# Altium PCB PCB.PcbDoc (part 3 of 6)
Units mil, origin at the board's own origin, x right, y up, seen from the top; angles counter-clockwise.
Board outline 7100 x 7000 mil, 4 copper layers (Top Layer, GND, VCC, Bottom Layer), stack 61.2 mil thick; 759 components, 507 nets, 2200 pads, 452 vias.
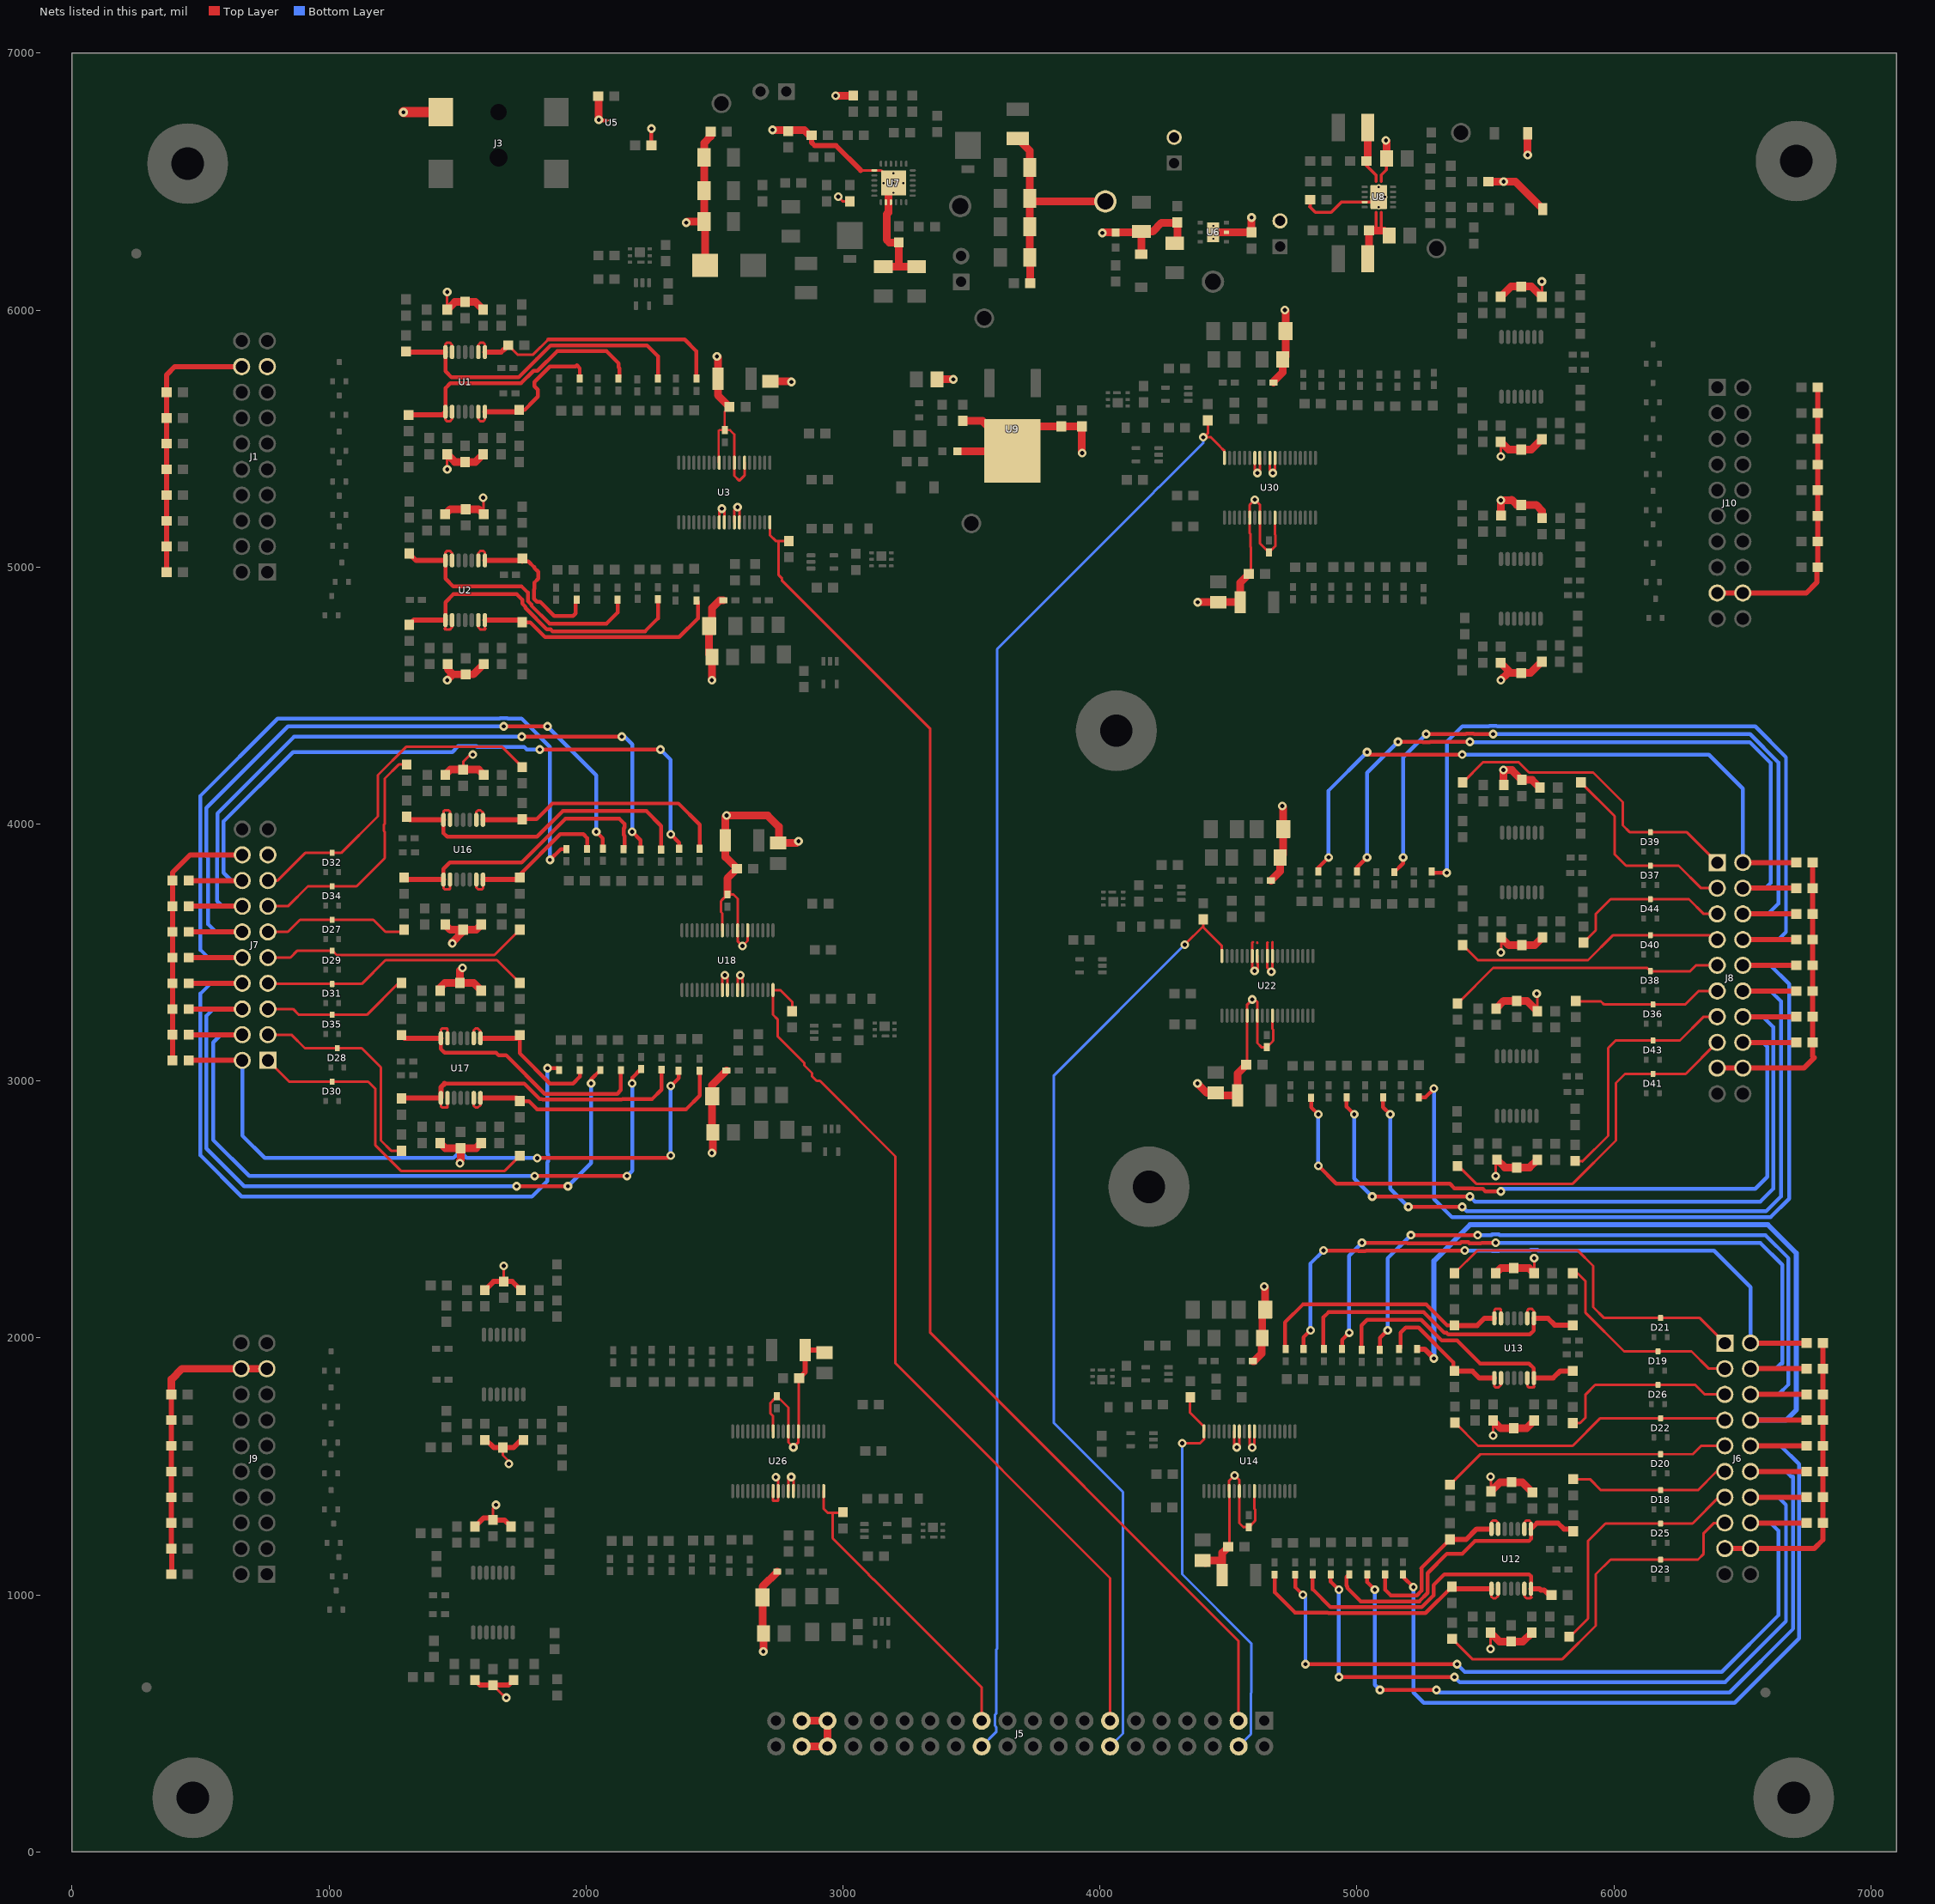
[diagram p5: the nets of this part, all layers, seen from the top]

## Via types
v1: diameter 34, hole 16, Top Layer to Bottom Layer, 440 vias
v2: diameter 19.68, hole 7.87, Top Layer to Bottom Layer, 11 vias
v3: diameter 30, hole 14, Top Layer to Bottom Layer, 1 vias

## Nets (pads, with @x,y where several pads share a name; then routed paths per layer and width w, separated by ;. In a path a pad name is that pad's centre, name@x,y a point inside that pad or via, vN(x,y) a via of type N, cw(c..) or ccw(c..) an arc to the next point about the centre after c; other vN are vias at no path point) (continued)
AGND: C1.1 C2.1 C3.1 C4.1 C5.2 C6.2 C7.2 C11.1 C12.1 C17.1 C18.1 C24.2 C25.2 C26.2 C30.1 C31.1 C35.1 C36.1 C39.2 C40.2 C41.2 C42.2 C43.2 C44.2 C45.2 C46.2 C47.2 C48.2 C49.1 C51.1 C53.2 C54.2 C55.2 C56.2 C57.2 C58.2 C59.2 C60.2 C62.1 C63.2 C64.2 C66.2 C67.2 C68.1 C69.2 C72.2 C73.2 C74.2 C76.1 C77.1 C78.1 C79.1 C80.2 C81.2 C82.2 C86.1 C87.1 C92.1 C93.1 C99.2 C100.2 C101.2 C105.1 C106.1 C110.1 C111.1 C114.1 C115.1 C116.1 C117.1 C118.2 C119.2 C120.2 C124.1 C125.1 C130.1 C131.1 C137.2 C138.2 C139.2 C143.1 C144.1 C148.1 C149.1 C152.1 C153.1 C154.1 C155.1 C156.2 C157.2 C158.2 C162.1 C163.1 C168.1 C169.1 C175.2 C176.2 C177.2 C181.1 C182.1 C186.1 C187.1 C190.1 C191.1 C192.1 C193.1 C194.2 C195.2 C196.2 C200.1 C201.1 C206.1 C207.1 C213.2 C214.2 C215.2 C219.1 C220.1 C224.1 C225.1 C228.1 C229.1 C230.1 C231.1 C232.2 C233.2 C234.2 C238.1 C239.1 C244.1 C245.1 C251.2 C252.2 C253.2 C257.1 C258.1 C262.1 C263.1 C272.2 C273.2 D11.2 D12.2 D13.2 D14.1 D17.2 J1.17 J1.18 J3.2 J5.35 J5.36 J5.37 J5.38 J6.17 J6.18 J7.17 J7.18 J8.17 J8.18 J9.17 J9.18 J10.17 J10.18 J11.2 J12.2 L2.2 R5.1 R6.1 R7.1 R8.1 R9.1 R10.1 R11.1 R12.1 R50.2 R63.1 R70.1 R77.1 R78.1 R79.1 R80.1 R81.1 R82.1 R83.1 R84.1 R122.1 R123.1 R124.1 R125.1 R126.1 R127.1 R128.1 R129.1 R167.1 R168.1 R169.1 R170.1 R171.1 R172.1 R173.1 R174.1 R212.1 R213.1 R214.1 R215.1 R216.1 R217.1 R218.1 R219.1 R257.1 R258.1 R259.1 R260.1 R261.1 R262.1 R263.1 R264.1 R313.1 R318.1 R323.1 R328.1 R333.1 R338.1 TP3.1 U3.6 U3.8 U3.11 U3.28 U3.29 U3.31 U3.32 U5.B1 U6.2 U6.7 U7.2 U7.3 U7.19 U7.25 U8.4 U8.11@5085.39,6440 U9.4@3660,5451.57 U14.6 U14.8 U14.11 U14.28 U14.29 U14.31 U14.32 U18.6 U18.8 U18.11 U18.28 U18.29 U18.31 U18.32 U22.6 U22.8 U22.11 U22.28 U22.29 U22.31 U22.32 U26.6 U26.8 U26.11 U26.28 U26.29 U26.31 U26.32 U30.6 U30.8 U30.11 U30.28 U30.29 U30.31 U30.32 | length 28220.3
  Top Layer w6: 2079,6738.19 U5.B1@2092.13,6738.19
  Top Layer w8: U3.11@2518.57,5406.14 2516.67,5408.05 2516.67,5437.83 2515.76,5437.83 2515.76,5530.26 2519.5,5534 2520.88,5532.62 R313.1@2540,5532.62 ; C26.2@2558.5,5623.26 2540,5604.75 R313.1@2540,5532.62 ; 2577.63,5516 2561.01,5532.62 R313.1@2540,5532.62
  Top Layer w10: v1(1460,5380) C3.1@1460,5438.82 ; C35.1@1460,6001.81 v1(1460,6070) ; C114.1@1522.36,4211.5 1522.36,4242.36 1550,4270 v1(1560,4270) ; v1(1600,5270) 1602,5268 C30.1@1602,5205.18 ; C201.1@1638.26,648.45 1676.71,610 1680,610 v1(1690,600) ; C191.1@1638.26,1291.45 1638.26,1338.26 v1(1650,1350) ; C200.1@1676.96,1572.9 1676.96,1543.04 1700,1520 v1(1700,1510) ; C190.1@1679.76,2219.42 1680,2219.67 v1(1680,2280) ; v1(2050,6740) 2060,6740 v1@2061.81,6738.19 ; U3.28@2518.57,5173.86 2518.57,5216.57 v1(2529,5227) 2538.26,5217.74 U3.29@2538.26,5173.86 ; U18.28@2530.93,3353.8 2530.93,3401.93 v1(2541,3412) 2550.62,3402.38 U18.29@2550.62,3353.8 ; U18.11@2530.93,3586.09 2530.93,3651.68 2525.32,3657.3 2525.32,3699.46 2529.12,3703.27 2529.12,3705.08 2529.46,3705.08 R323.1@2550,3725.62 2573.98,3725.62 2590.63,3708.97 2590,3600.92 U18.8@2589.08,3600 ; U3.31@2577.63,5173.86 2577.63,5220.63 v1(2590,5233) 2597.31,5225.69 U3.32@2597.31,5173.86 ; 2577.63,5516 U3.8@2577.63,5406.14 2577.63,5355.37 2597,5336 2617,5356 U3.6@2617,5406.14 ; U18.31@2589.99,3353.8 2589.99,3401.99 2600,3412 v1(2601,3412) 2601,3411 2609.67,3402.33 U18.32@2609.67,3353.8 ; U18.8@2589.99,3586.09 2589.99,3544.01 v1(2609,3525) 2629.36,3545.36 U18.6@2629.36,3586.09 ; U26.28@2728.57,1403.81 2728.57,1366.72 2728.26,1366.41 2748.26,1366.41 U26.29@2748.26,1403.81 2748.26,1448.74 v1(2739,1458) ; U26.11@2728.57,1636.09 2728.57,1697.76 2725.86,1697.76 2718.32,1705.3 2718.32,1747.46 2725.86,1755 2728.57,1755 2728.57,1759.19 R333.1@2743,1773.62 2787.63,1729 U26.8@2787.63,1636.09 2787.63,1593.37 v1(2807,1574) 2827,1594 U26.6@2827,1636.09 ; U26.31@2787.63,1403.81 2787.63,1452.11 2794.52,1459 v1(2799,1459) 2799,1454.52 2807.31,1446.21 U26.32@2807.31,1403.81 U26.32@2808.22,1404.71 ; U26.6@2826.09,1639.95 2827.9,1641.76 2827.9,1841.41 C215.2@2829.75,1843.26 ; v1(2982,6441) 2982,6440 2998.93,6423.07 R50.2@3026.93,6423.07 ; 3066.22,6543.78 U7.19@3122.13,6543.78 3147.72,6543.78 v2(3196.93,6494.57) 3187.09,6484.73 U7.25@3187.09,6456.18 ; C101.2@4499.5,1187 4504.21,1191.71 4504.21,1402.95 U14.6@4503.31,1403.86 4503.31,1444.31 v1(4524,1465) 4525,1465 4542.68,1447.32 U14.8@4542.68,1403.86 4542.68,1279.01 4559.5,1262.19 4560.87,1263.57 R318.1@4580,1263.57 4603.21,1286.78 4603.54,1286.78 4603.54,1288.59 4604.68,1289.73 4604.68,1331.89 4601.73,1334.84 U14.11@4601.73,1403.86 ; U14.32@4522.99,1636.14 4522.99,1584.01 v1(4533,1574) 4542.68,1583.68 U14.31@4542.68,1636.14 ; C177.2@4569.5,3063 4573.31,3066.8 U22.6@4573.31,3254.17 4573.31,3297.31 v1(4593,3317) 4603,3317 4612.68,3307.32 U22.8@4612.68,3254.17 4612.68,3147.32 4628.62,3131.38 R328.1@4650,3131.38 4673.21,3154.59 4673.54,3154.59 4673.54,3156.4 4674.69,3157.54 4674.69,3199.7 4671.73,3202.66 U22.11@4671.73,3254.17 ; C253.2@4579.5,4973 4588.5,4982 4588.5,5075.32 4586.77,5077.05 4586.77,5127.95 4582.13,5132.6 4582.13,5162.89 4582.24,5163.01 4582.24,5168.6 4584.06,5170.41 U30.6@4584.06,5180 ; U14.29@4582.05,1636.14 4582.05,1582.95 4592,1573 v1(4593,1573) 4593,1574 4601.73,1582.73 U14.28@4601.73,1636.14 ; U30.6@4583.15,5192.44 4583.15,5242.15 v1(4603,5262) 4622.52,5242.48 U30.8@4622.52,5192.44 4622.52,5091.86 R338.1@4658,5056.38 4658,5056.75 4682.69,5081.43 4682.69,5124.7 4681.57,5125.81 U30.11@4681.57,5192.44 ; 4595.49,3540.92 4592.99,3538.42 U22.32@4592.99,3486.46 4592.99,3437.01 v1(4602,3428) 4605,3428 4614,3437 4614,3456.61 4613.58,3457.02 4613.58,3485.55 U22.31@4612.68,3486.46 ; U30.32@4602.83,5424.72 4602.83,5376.17 v1(4613,5366) 4622.52,5375.52 U30.31@4622.52,5424.72 ; 4612,3538 4612.68,3537.32 ; 4653,3539 4652.05,3538.05 U22.29@4652.05,3486.46 4652.05,3439.95 v1(4667,3425) 4671.73,3429.73 U22.28@4671.73,3486.46 4671.73,3539.27 4671,3540 ; U30.29@4661.89,5424.72 4661.89,5376.11 4672,5366 v1(4673,5366) 4673,5367 4681.57,5375.57 U30.28@4681.57,5424.72 ; v1(5520,790) 5520.73,790.73 C106.1@5520.73,852.95 ; v1(5520,1460) 5522.05,1457.95 C92.1@5522.05,1403.19 ; v1(5530,1620) C105.1@5530,1678.5 ; v1(5540,2630) 5540,2688.48 C182.1@5545,2693.49 ; v1@5559.69,4560.31 v1(5560,4560) ; C257.1@5559.69,5487.48 5559.69,5430.31 v1(5560,5430) ; v1(5560,3500) 5562.05,3502.05 C181.1@5562.05,3558.5 ; C79.1@5690,2251.5 v1(5690,2310) ; v1(5700,3340) 5702.05,3337.95 C154.1@5702.05,3271.5 ; C231.1@5719.69,6051.5 5720,6051.81 v1(5720,6111.02)
  Top Layer w12: C67.2@4818.5,6430 4818.5,6405.24 4816,6402.73 4838.73,6380 4900,6380 4940.31,6420.31 U8.4@5030.28,6420.31 5065.71,6420.31 U8.11@5085.39,6440 ; C63.2@5036.89,6580 5036.89,6563.11 5075.55,6524.45 5075.55,6500.24 ; 5070,6310 5075.55,6315.55 5075.55,6379.76 ; 5087.7,6310 5095.24,6317.54 5095.24,6379.76 ; 5095.24,6500.24 5095.24,6525.24 5115.39,6545.39 C64.2@5115.39,6590
  Top Layer w15: v1@2061.81,6738.19 2079,6738.19 ; C272.2@2254.5,6641 2254.5,6693.5 v1@2255,6694
  Top Layer w20: R7.1@368.5,4980 R8.1@368.5,5080 R9.1@368.5,5180 R10.1@368.5,5280 R11.1@368.5,5380 R12.1@368.5,5480 R5.1@368.5,5580 R6.1@368.5,5680 368.5,5748.5 400,5780 J1.18@660,5780 ; R213.1@386.76,1779.95 R212.1@386.76,1679.95 R219.1@386.76,1579.95 R218.1@386.76,1479.95 R217.1@386.76,1379.95 R216.1@386.76,1279.95 386.76,1181.62 388.43,1179.95 R214.1@388.43,1079.95 ; R124.1@390.87,3080 R125.1@390.87,3180 R126.1@390.87,3280 R127.1@390.87,3380 R128.1@390.87,3480 R129.1@390.87,3580 R122.1@390.87,3680 R123.1@390.87,3780 390.87,3810.87 460,3880 J7.18@662.36,3880 ; C193.1@1568.26,668.45 1588.26,648.45 C201.1@1638.26,648.45 1698.26,648.45 C207.1@1718.26,668.45 ; C225.1@1568.26,1265.9 1602.31,1299.95 1629.75,1299.95 C191.1@1638.26,1291.45 1682.71,1291.45 C219.1@1708.26,1265.9 ; C224.1@1606.96,2185.9 1640.48,2219.42 C190.1@1679.76,2219.42 1713.43,2219.42 C220.1@1746.96,2185.9 ; C192.1@1609.76,1604.93 1641.79,1572.9 C200.1@1676.96,1572.9 1717.73,1572.9 C206.1@1749.76,1604.93 ; C194.2@2687.08,854.2 C194.2@2691.33,849.95 ; C215.2@2829.75,1843.26 2853.22,1866.72 C214.2@2853.22,1953.26 2918.26,1953.26 C213.2@2928.26,1943.26 ; C51.1@2878.5,6680 2878.5,6651.5 2890,6640 2970,6640 ; 2972.78,6640 3069,6543.78 ; J8.17@6402.05,3050 J8.18@6502.05,3050 6739.69,3050 6779.69,3090 6773.54,3096.14 R168.1@6773.54,3150 R167.1@6773.54,3250 R174.1@6773.54,3350 R173.1@6773.54,3450 R172.1@6773.54,3550 R171.1@6773.54,3650 R170.1@6773.54,3750 R169.1@6773.54,3850 ; J10.17@6402.05,4898.98 J10.18@6502.05,4898.98 6748.98,4898.98 6790,4940 6790,4995.43 R258.1@6793.54,4998.98 R257.1@6793.54,5098.98 R264.1@6793.54,5198.98 R263.1@6793.54,5298.98 R262.1@6793.54,5398.98 R261.1@6793.54,5498.98 R260.1@6793.54,5598.98 R259.1@6793.54,5698.98 ; J6.17@6432.05,1180 J6.18@6532.05,1180 6779.69,1180 6813.54,1213.86 R78.1@6813.54,1280 R77.1@6813.54,1380 R84.1@6813.54,1480 R83.1@6813.54,1580 R82.1@6813.54,1680 R81.1@6813.54,1780 R80.1@6813.54,1880 R79.1@6813.54,1980
  Top Layer w30: R213.1@386.76,1779.95 386.76,1838.45 428.26,1879.95 J9.18@658.26,1879.95 J9.17@758.26,1879.95 ; C117.1@1432.36,2758.5 1452.36,2738.5 C125.1@1512.36,2738.5 ; C149.1@1432.36,3351.5 1432.36,3362.36 1451.5,3381.5 C115.1@1510,3381.5 ; C36.1@1452,5205.18 1472,5225.18 C2.1@1532,5225.18 1582,5225.18 C30.1@1602,5205.18 ; C116.1@1452.36,3608.5 1472.36,3588.5 C124.1@1522.36,3588.5 ; C148.1@1452.36,4191.5 1472.36,4211.5 C114.1@1522.36,4211.5 1582.36,4211.5 C144.1@1602.36,4191.5 ; v1(1460,4560) 1482.19,4582.19 ; C3.1@1460,5438.82 1490,5408.82 C11.1@1530,5408.82 1570,5408.82 C17.1@1600,5438.82 ; C35.1@1460,6001.81 1490,6031.81 C1.1@1530,6031.81 1570,6031.81 C31.1@1600,6001.81 ; C4.1@1462,4622.19 1462,4602.38 1482.19,4582.19 ; v1(1480,3535) 1480,3540 1522.36,3582.36 C124.1@1522.36,3588.5 ; v1(1510,2680) 1510,2690 1512.36,2692.36 C125.1@1512.36,2738.5 ; v1(1520.05,3440) 1510,3429.95 C115.1@1510,3381.5 ; C131.1@1592.36,2758.5 1572.36,2738.5 C125.1@1512.36,2738.5 ; C143.1@1592.36,3351.5 1562.36,3381.5 C115.1@1510,3381.5 ; C130.1@1592.36,3608.5 1572.36,3588.5 C124.1@1522.36,3588.5 ; C18.1@1602,4622.19 1562,4582.19 C12.1@1532,4582.19 1482.19,4582.19 ; C273.2@2048.5,6827 2050,6825.5 v1(2050,6740) ; v1(2390,6340) 2394.25,6344.25 C45.2@2459.84,6344.25 ; C42.2@2463.43,6174.25 2463.43,6340.67 C45.2@2459.84,6344.25 ; C46.2@2485.43,6694.25 2485.43,6675.43 2459.84,6649.84 C43.2@2459.84,6594.25 C44.2@2459.84,6464.25 C45.2@2459.84,6344.25 ; v1(2490,2720) 2493.69,2723.69 C118.2@2493.69,2799.95 2491.18,2802.46 C119.2@2491.18,2940 2491.18,2984.18 C120.2@2547,3040 ; v1(2490,4560) C5.2@2490,4650 2478.82,4661.18 C6.2@2478.82,4770 2490,4781.18 2490,4840 2520,4870 C7.2@2534.63,4870 ; v1(2510,5820) 2513.3,5816.7 C25.2@2513.3,5733.26 2513.3,5668.47 C26.2@2558.5,5623.26 ; R323.1@2550,3725.62 2550,3788.39 C139.2@2587.87,3826.26 2542.66,3871.47 C138.2@2542.66,3936.26 2542.66,4028.66 v1(2547,4033) 2707,4033 2751,3989 2751,3929.64 C137.2@2747.62,3926.26 2820.26,3926.26 v1(2827,3933) ; C194.2@2687.08,854.2 C195.2@2687.08,989.95 2687.08,1032.39 C196.2@2744.63,1089.95 ; v1(2690,780) 2691.33,781.33 C194.2@2691.33,849.95 ; C24.2@2718.26,5723.26 2796.74,5723.26 v1(2800,5720) ; v1(2726,6701) 2781.99,6701 C60.2@2786.93,6696.06 2790.87,6700 2850.02,6700 2870.02,6680 C51.1@2878.5,6680 ; J5.38@2840,410 J5.36@2940,410 J5.35@2940,510 J5.37@2840,510 ; v1(2972,6834) 2980.47,6834 2981.24,6834.76 C49.1@3040,6834.76 ; C47.2@3156.93,6168.74 3220,6168.74 ; U7.25@3187.09,6484.73 3178,6475.64 3178,6431 3177,6430 3177,6380 3170,6373 3170,6274 3180.93,6263.07 C55.2@3216.93,6263.07 3216.93,6171.81 3220,6168.74 ; C56.2@3286.93,6168.74 3220,6168.74 ; R70.1@3366.18,5730.39 3429.61,5730.39 v1(3430,5730) ; D17.2@3445.71,5450.39 3658.82,5450.39 U9.4@3660,5451.57 ; C72.2@3466.18,5568.9 3542.68,5568.9 U9.4@3660,5451.57 ; L2.2@3680,6667.48 3727.09,6620.4 C57.2@3727.09,6554.57 C58.2@3727.09,6434.57 ; C53.2@3731.4,6101.6 C53.2@3728.43,6104.57 3728.43,6203.23 C54.2@3727.09,6204.57 C59.2@3727.09,6324.57 C58.2@3727.09,6434.57 ; v1(3931,5444) 3930,5445 C74.2@3930,5547.2 C73.2@3850,5547.2 3755.63,5547.2 U9.4@3660,5451.57 ; v1(4010,6300) 4012.28,6302.28 D13.2@4061.32,6302.28 4157.93,6302.28 C39.2@4161.32,6305.67 ; TP3.1@4021.32,6422.76 3738.9,6422.76 C58.2@3727.09,6434.57 ; D12.2@4161.32,6217.22 C39.2@4161.32,6305.67 ; C41.2@4291.32,6259.84 4301.32,6269.84 C40.2@4301.32,6341.26 4300.06,6340 4240,6340 4205.67,6305.67 C39.2@4161.32,6305.67 ; v1(4380,2990) 4417,2953 C175.2@4451,2953 4461,2943 C176.2@4536.04,2943 4536.04,3029.54 C177.2@4569.5,3063 ; v1(4381,4863) C251.2@4461,4863 C252.2@4546.04,4863 4546.04,4939.54 C253.2@4579.5,4973 ; C99.2@4410,1124 C99.2@4400,1134 4474.04,1134 4476.04,1136 ; U6.7@4441.32,6302.76 U6.2@4492.3,6302.76 4589.55,6302.76 C48.2@4590,6302.3 v1(4590,6360) ; C100.2@4476.04,1077 4476.04,1136 ; C101.2@4499.5,1187 4476.04,1163.54 4476.04,1136 ; C82.2@4595.67,1910 4600,1910 4630,1940 4630,1997.95 C80.2@4632.05,2000 4632.05,2098.82 C81.2@4643.23,2110 4643.23,2196.77 v1(4640,2200) ; C158.2@4665.67,3780 4702.05,3816.38 C156.2@4702.05,3870 4713.23,3881.18 C157.2@4713.23,3980 4713.23,4066.77 v1(4710,4070) ; C234.2@4675.51,5718.26 4675.51,5721.73 4711.89,5758.11 C232.2@4711.89,5808.26 4723.07,5819.44 C233.2@4723.07,5918.26 4723.07,5996.93 v1(4720,6000) ; C63.2@5036.89,6580 5042.48,6585.59 C62.1@5042.48,6710 ; C68.1@5042.48,6200 5046.89,6204.41 C69.2@5046.89,6310 5070,6310 5087.7,6310 5105.39,6310 C66.2@5125.39,6290 ; v1(5113,6660) 5115.39,6657.61 C64.2@5115.39,6590 ; R63.1@5511.5,6500 v1(5571,6500) 5616.47,6500 D14.1@5723.47,6393 ; C106.1@5520.73,852.95 5555.18,818.5 C76.1@5600.73,818.5 5646.28,818.5 C110.1@5680.73,852.95 ; C92.1@5522.05,1403.19 5557.6,1438.74 C86.1@5602.05,1438.74 5643.35,1438.74 C78.1@5683.35,1398.74 ; C105.1@5530,1678.5 5560,1648.5 C77.1@5610,1648.5 5660,1648.5 C111.1@5690,1678.5 ; C93.1@5540,2251.5 5560,2271.5 C87.1@5610,2271.5 5670,2271.5 C79.1@5690,2251.5 ; C168.1@5542.05,3281.5 5572.05,3311.5 C162.1@5622.05,3311.5 5662.05,3311.5 C154.1@5702.05,3271.5 ; C182.1@5545,2693.49 5575.54,2662.95 C152.1@5622.05,2662.95 5672.05,2662.95 C186.1@5702.05,2692.95 ; C258.1@5559.69,4627.48 5599.69,4587.48 ; C257.1@5559.69,5487.48 5589.69,5457.48 C229.1@5639.69,5457.48 5679.69,5457.48 C263.1@5719.69,5497.48 ; C245.1@5559.69,6051.5 5599.69,6091.5 C239.1@5639.69,6091.5 5679.69,6091.5 C231.1@5719.69,6051.5 ; v1(5560,4560) 5587.48,4587.48 5599.69,4587.48 ; C244.1@5560.98,5200.47 5560,5201.46 v1(5560,5260) 5599.93,5260 5602.05,5262.13 5602.29,5262.13 5622.92,5241.5 C238.1@5640,5241.5 5697.46,5241.5 5720.98,5217.97 C230.1@5720.98,5190.47 ; C181.1@5562.05,3558.5 5592.05,3528.5 C153.1@5642.05,3528.5 5692.05,3528.5 C187.1@5722.05,3558.5 ; C169.1@5572.05,4151.5 5570,4153.54 v1(5570,4210) 5603.54,4210 C163.1@5642.05,4171.5 5682.05,4171.5 C155.1@5712.05,4141.5 ; D11.2@5664.47,6688 5664.47,6605.53 5666,6604 v1(5665,6603) ; C262.1@5719.69,4631.93 5675.24,4587.48 C228.1@5639.69,4587.48 5599.69,4587.48
  Top Layer w40: v1(1290,6770) 1290.08,6770.08 J3.2@1435.59,6770.08
  other v1: 2255,6706
  other v2: 4441.32,6277.76 4441.32,6327.76 5085.39,6400.63 5060.79,6440 5110,6440 3196.93,6456.18 5085.39,6479.37 3158.54,6494.57 3235.32,6494.57 3196.93,6532.95
AO0+: C13.1 R13.1 U1.8 U1.9 | length 1146.8
  Top Layer w10: U1.8@1453.23,5604.17 1453.23,5573.54 1460,5566.77 1470,5566.77 1478.82,5575.59 U1.9@1478.82,5604.17
  Top Layer w15: U1.8@1453.23,5604.17 1453.23,5696.23 1472,5715 1746.87,5715 1795.87,5764 1811.65,5764 1887.65,5840 2080,5840 2127.63,5792.37 2127.63,5776.59 2130,5774.22 2130,5737.87 R13.1@2125.76,5733.62
  Top Layer w20: C13.1@1310,5591.81 1440.87,5591.81 U1.8@1453.23,5604.17
AO1+: C22.1 R15.1 U1.13 U1.14 | length 632.3
  Top Layer w10: U1.13@1581.18,5604.17 1581.18,5575.59 1590,5566.77 1600,5566.77 1606.77,5573.54 U1.14@1606.77,5604.17
  Top Layer w15: C22.1@1740,5611.81 1761.81,5611.81 1800,5650 1800,5650.22 1813.37,5663.59 1813.37,5690.41 1800,5703.78 1800,5720 1860,5780 1960,5780 1965,5785 1975.78,5774.22 R15.1@1975.78,5733.62
  Top Layer w20: U1.14@1606.77,5604.17 1732.36,5604.17 C22.1@1740,5611.81
AO2+: C32.1 R22.1 U2.1 U2.2 | length 678.2
  Top Layer w10: U2.2@1581.18,5025.83 1581.18,5054.41 1590,5063.23 1600,5063.23 1606.77,5056.46 U2.1@1606.77,5025.83
  Top Layer w15: C32.1@1752,5022.19 1775.81,5022.19 1798.81,4999.19 1798.81,4996.98 1814.37,4981.41 1814.37,4954.59 1798.81,4939.02 1798.81,4914.59 1797.63,4913.41 1797.63,4876.59 1810,4864.22 1821.78,4864.22 1876,4810 1950,4810 1960,4820 1960,4868.84 R22.1@1963.5,4872.34
  Top Layer w20: U2.1@1606.77,5025.83 1748.36,5025.83 C32.1@1752,5022.19
AO3+: C38.1 R25.1 U2.6 U2.7 | length 1146.9
  Top Layer w10: U2.7@1453.23,5025.83 1453.23,5056.46 1460,5063.23 1470,5063.23 1478.82,5054.41 U2.6@1478.82,5025.83
  Top Layer w15: U2.7@1453.23,5025.83 1453.23,4954.77 1483.93,4924.07 1750,4924.07 1772.07,4902 1774.75,4902 1774.75,4867.12 1787.13,4854.74 1787.13,4850.53 1857.65,4780 2080,4780 2123.52,4823.52 R25.1@2123.52,4872.34
  Top Layer w20: C38.1@1312,5052.19 1338.36,5025.83 U2.7@1453.23,5025.83
AO4+: C14.1 R27.1 U2.8 U2.9 | length 1321.4
  Top Layer w10: U2.8@1453.23,4793.54 1453.23,4763.23 1450,4760 1453.86,4756.14 1470,4756.14 1478.82,4764.96 U2.9@1478.82,4793.54
  Top Layer w15: U2.8@1453.23,4793.54 1453.23,4863.23 1484,4894 1731,4894 1751.88,4873.12 1751.88,4857.64 1764.25,4845.27 1764.25,4841.05 1848.18,4757.13 1862.87,4757.13 1870,4750 2230,4750 2280,4800 R27.1@2280,4873.98
  Top Layer w20: C14.1@1312,4775.18 1330.36,4793.54 U2.8@1453.23,4793.54
AO5+: C23.1 R29.1 U2.13 U2.14 | length 1056.7
  Top Layer w10: U2.13@1581.18,4793.54 1581.18,4764.96 1590,4756.14 1606.14,4756.14 1610,4760 1606.77,4763.23 U2.14@1606.77,4793.54
  Top Layer w15: C23.1@1752,4785.18 1782.47,4785.18 1840.53,4727.13 2363.01,4727.13 2435.89,4800 2435.89,4864.06 R29.1@2430,4869.95
  Top Layer w20: U2.14@1606.77,4793.54 1743.64,4793.54 C23.1@1752,4785.18
AO6+: C33.1 R31.1 U1.1 U1.2 | length 1090.6
  Top Layer w10: U1.2@1581.18,5836.46 1581.18,5865.04 1590,5873.86 1600,5873.86 1606.77,5867.09 U1.1@1606.77,5836.46 ; C33.1@1697.5,5863 1733.5,5827 1794.65,5827 1853.4,5885.75
  Top Layer w15: 1853.4,5885.75 2384.25,5885.75 2430,5840 R31.1@2430,5733.06
  Top Layer w20: U1.1@1606.77,5836.46 1670.14,5836.46 1679.55,5845.87 1680.38,5845.87 C33.1@1697.5,5863
AO7+: C37.1 R33.1 U1.6 U1.7 | length 1312.8
  Top Layer w10: U1.7@1453.23,5836.46 1453.23,5867.09 1460,5873.86 1470,5873.86 1478.82,5865.04 U1.6@1478.82,5836.46
  Top Layer w15: U1.7@1453.23,5836.46 1453.23,5761.77 1477.13,5737.87 1737.39,5737.87 1807.64,5808.12 1808.12,5808.12 1862.87,5862.87 2237.13,5862.87 2280,5820 2280,5750 2280.21,5749.79 R33.1@2280.21,5733.62
  Top Layer w20: C37.1@1300,5838.82 1302.36,5836.46 U1.7@1453.23,5836.46
B0+: D18.3 J6.11 R73.1 | length 637.8
  Top Layer w10: R73.1@5842.05,1450.24 5907.16,1450.24 5950,1407.4 D18.3@6182.05,1407.4 6327.09,1407.4 6399.69,1480 J6.11@6432.05,1480
B0-: J6.12 R84.2 R86.1 | length 3170.5
  Top Layer w15: R86.1@5040,1080 5040,1050 v1(5070,1020) ; v1(5090,630) v1(5310,630)
  Top Layer w20: J6.12@6532.05,1480 R84.2@6750.55,1480
  Bottom Layer w15: v1(5070,1020) 5070,650 v1(5090,630) ; v1(5310,630) 5320,620 6450,620 6698.15,868.15 6698.15,1460 6690,1460 6670,1480 J6.12@6532.05,1480
B1+: D20.3 J6.9 R90.1 | length 1132.7
  Top Layer w10: R90.1@5362.05,1428.74 5480.71,1547.4 D20.3@6182.05,1547.4 6307.09,1547.4 6339.69,1580 J6.9@6432.05,1580
B1-: J6.10 R83.2 R89.1 | length 3212.7
  Top Layer w15: R89.1@5180,1080 5180,1070 v1(5220,1030)
  Top Layer w20: J6.10@6532.05,1580 R83.2@6750.55,1580
  Bottom Layer w15: v1(5220,1030) 5220,620 5260,580 6470,580 6721.02,831.02 6721.02,1508.54 6649.57,1580 J6.10@6532.05,1580
B2+: D22.3 J6.7 R107.1 | length 1134.9
  Top Layer w10: R107.1@5382.05,1670.14 5472.18,1580 5840,1580 5947.4,1687.4 D22.3@6182.05,1687.4 6424.65,1687.4 J6.7@6432.05,1680
B2-: J6.8 R82.2 R96.1 | length 2997.2
  Top Layer w20: R96.1@5234.45,1956.42 5263.58,1956.42 v1(5300,1920) ; J6.8@6532.05,1680 R82.2@6750.55,1680
  Bottom Layer w20: v1(5300,1920) 5300,2300 5440,2440 6600,2440 6710,2330 6710,1720 6670,1680 J6.8@6532.05,1680
B3+: D26.3 J6.5 R116.1 | length 721.9
  Top Layer w10: R116.1@5840,1668.5 5868.5,1668.5 5890,1690 5890,1780 5927.4,1817.4 D26.3@6172.05,1817.4 6316.69,1817.4 6354.09,1780 J6.5@6432.05,1780
B3-: J6.6 R81.2 R98.1 | length 2879.7
  Top Layer w15: R98.1@5088.5,1953.62 5088.5,1968.5 5090,1970 5090,2000 v1(5120,2030) ; v1(5210,2400) v1(5470,2400)
  Top Layer w20: J6.6@6532.05,1780 R81.2@6750.55,1780
  Bottom Layer w15: v1(5120,2030) 5120,2310 v1(5210,2400) ; v1(5470,2400) 5524.22,2400 5526.59,2402.37 5553.41,2402.37 5555.78,2400 6590,2400 6680,2310 6680,1818.7 6641.3,1780 J6.6@6532.05,1780
B4+: D19.3 J6.3 R75.1 | length 817.8
  Top Layer w10: R75.1@5840,2251.5 5858.5,2251.5 5890,2220 5890,2097.25 6039.85,1947.4 D19.3@6172.05,1947.4 6302.28,1947.4 6369.69,1880 J6.3@6432.05,1880
B4-: J6.4 R80.2 R100.1 | length 2856.9
  Top Layer w15: R100.1@4942.5,1956.42 4942.5,1992.5 v1(4970,2020) ; v1(5020,2370) 5194.22,2370 5196.59,2367.63 5401.84,2367.63 5406.59,2372.37 5433.41,2372.37 5438.16,2367.63 5483.41,2367.63 5485.78,2370 v1(5540,2370)
  Top Layer w20: J6.4@6532.05,1880 R80.2@6750.55,1880
  Bottom Layer w15: v1(4970,2020) 4970,2320 v1(5020,2370) ; v1(5540,2370) 6570,2370 6655.28,2284.72 6655.28,1900 6650,1900 6630,1880 J6.4@6532.05,1880
B5+: D21.3 J6.1 R92.1 | length 1331.4
  Top Layer w10: R92.1@5380,2251.5 5468.38,2339.87 5860.13,2339.87 5920,2280 5920,2120 5962.6,2077.4 D21.3@6182.05,2077.4 6334.65,2077.4 J6.1@6432.05,1980
B5-: J6.2 R79.2 R102.1 | length 2578.9
  Top Layer w15: R102.1@4792.5,1956.42 4792.5,2002.5 v1(4820,2030) ; v1(4870,2340) 5004.22,2340 5006.59,2337.63 5033.41,2337.63 5035.78,2340 v1(5420,2340)
  Top Layer w20: J6.2@6532.05,1980 R79.2@6750.55,1980
  Bottom Layer w15: v1(4820,2030) 4820,2290 v1(4870,2340) ; v1(5420,2340) 5524.22,2340 5526.59,2337.63 5553.41,2337.63 5555.78,2340 5674.22,2340 5676.59,2342.37 5703.41,2342.37 5705.78,2340 6390,2340 6532.05,2197.95 J6.2@6532.05,1980
B6+: D23.3 J6.15 R109.1 | length 1477.4
  Top Layer w10: R109.1@5370.73,828.5 5449.23,750 5800,750 5930,880 5930,1080 5987.4,1137.4 D23.3@6182.05,1137.4 6327.09,1137.4 6349.69,1160 6349.69,1240 6389.69,1280 J6.15@6432.05,1280
B6-: J6.16 R78.2 R104.1 | length 2977.7
  Top Layer w15: R104.1@4760,1078.7 4760,1030 v1(4790,1000) ; v1(4800,730) v1(5390,730)
  Top Layer w20: J6.16@6532.05,1280 R78.2@6750.55,1280
  Bottom Layer w15: v1(4790,1000) 4800,990 v1(4800,730) ; v1(5390,730) 5420,700 6420,700 6640,920 6640,1250 6610,1280 J6.16@6532.05,1280
B7+: D25.3 J6.13 R112.1 | length 1002.7
  Top Layer w10: R112.1@5830.73,838.5 5900,907.78 5900,1210 5967.4,1277.4 D25.3@6182.05,1277.4 6306.22,1277.4 6408.82,1380 J6.13@6432.05,1380
B7-: J6.14 R77.2 R106.1 | length 3081.5
  Top Layer w15: R106.1@4898.21,1080 4898.21,1051.79 v1(4930,1020) ; v1(4930,680) v1(5380,680)
  Top Layer w20: J6.14@6532.05,1380 R77.2@6750.55,1380
  Bottom Layer w15: v1(4930,680) v1(4930,1020) ; v1(5380,680) 5400,660 6432.91,660 6670,897.09 6670,1350 6640,1380 J6.14@6532.05,1380
BO0+: C88.1 R85.1 U12.8 U12.9 | length 1251.3
  Top Layer w10: U12.9@5651.91,1256.14 5651.91,1281.91 5660,1290 5670,1290 5677.5,1282.5 U12.8@5677.5,1256.14
  Top Layer w15: R85.1@4970,1080 4960,1070 4960,1035.78 4962.37,1033.41 4962.37,1027.63 5015.25,974.75 5242.88,974.75 5275.25,1007.12 5275.25,1084.75 5275,1085 5350,1160 5410,1160 5460,1210 5670,1210 5677.5,1217.5 U12.8@5677.5,1256.14
  Top Layer w20: U12.8@5677.5,1256.14 5700.72,1279.36 5782.64,1279.36 5805.86,1256.14 5825.23,1256.14 5830.5,1250.87 5838.43,1250.87 C88.1@5842.05,1247.24
BO1+: C97.1 R87.1 U12.13 U12.14 | length 729.1
  Top Layer w10: U12.14@5523.96,1256.14 5523.96,1283.96 5530,1290 5540,1290 5549.55,1280.45 U12.13@5549.55,1256.14
  Top Layer w15: R87.1@5110,1080 5110,1020 5132.37,997.63 5233.41,997.63 5252.37,1016.59 5252.37,1075.28 5252.13,1075.53 5252.13,1094.47 5252.37,1094.72 5252.37,1101.33 5250,1103.7 C97.1@5362.05,1215.75
  Top Layer w20: C97.1@5362.05,1215.75 5425.75,1215.75 5466.14,1256.14 U12.14@5523.96,1256.14
BO2+: C107.1 R94.1 U13.1 U13.2 | length 628.6
  Top Layer w10: U13.1@5535.28,1843.86 5535.28,1811.18 5540,1806.46 5550,1806.46 5560.87,1817.32 U13.2@5560.87,1843.86
  Top Layer w15: R94.1@5164.45,1956.42 5170,1961.97 5170,2020 5190,2040 5240,2040 5375,1905 5375,1876.5 C107.1@5380,1871.5
  Top Layer w20: C107.1@5380,1871.5 5381.5,1870 5450,1870 5476.14,1843.86 U13.1@5535.28,1843.86
BO3+: C113.1 R97.1 U13.6 U13.7 | length 1148.3
  Top Layer w10: U13.6@5663.23,1843.86 5663.23,1813.23 5670,1806.46 5686.46,1806.46 5690,1810 5688.82,1811.18 U13.7@5688.82,1843.86
  Top Layer w15: R97.1@5018.5,1953.62 5018.5,2048.5 5040,2070 5250,2070 5330,1990 5390,1990 5480,1900 5670,1900 5688.82,1881.18 U13.7@5688.82,1843.86
  Top Layer w20: U13.7@5688.82,1843.86 5763.86,1843.86 5791.5,1871.5 C113.1@5840,1871.5
BO4+: C89.1 R99.1 U13.8 U13.9 | length 1295.2
  Top Layer w10: U13.9@5663.23,2076.14 5663.23,2106.77 5670,2113.54 5680,2113.54 5688.82,2104.72 U13.8@5688.82,2076.14
  Top Layer w15: R99.1@4872.5,1956.42 4870,1958.93 4870,2080 4890,2100 5260,2100 5340,2020 5348.38,2020 5354.93,2013.44 5673.44,2013.44 5688.82,2028.82 U13.8@5688.82,2076.14
  Top Layer w20: U13.8@5688.82,2076.14 5743.86,2076.14 5770,2050 5838.5,2050 C89.1@5840,2048.5
BO5+: C98.1 R101.1 U13.13 U13.14 | length 1089.1
  Top Layer w10: U13.14@5535.28,2076.14 5535.28,2108.82 5540,2113.54 5556.46,2113.54 5560.87,2109.13 U13.13@5560.87,2076.14
  Top Layer w15: R101.1@4722.5,1956.42 4720,1958.93 4720,2060 4790,2130 5270,2130 5351.5,2048.5 C98.1@5380,2048.5
  Top Layer w20: C98.1@5380,2048.5 5468.5,2048.5 5496.14,2076.14 U13.14@5535.28,2076.14
BO6+: C108.1 R103.1 U12.1 U12.2 | length 1083.1
  Top Layer w10: U12.1@5523.96,1023.86 5523.96,992.5 5530,986.46 5540,986.46 5549.55,996 U12.2@5549.55,1023.86
  Top Layer w15: R103.1@4680,1078.7 4680,1010 4758.62,931.38 4886.27,931.38 4888.65,929 5267.51,929 C108.1@5370,1031.5
  Top Layer w20: C108.1@5370,1031.5 5377.64,1023.86 U12.1@5523.96,1023.86
BO7+: C112.1 R105.1 U12.6 U12.7 | length 1252.4
  Top Layer w10: U12.6@5651.91,1023.86 5651.91,994.55 5660,986.46 5676.46,986.46 5680,990 5677.5,992.5 U12.7@5677.5,1023.86
  Top Layer w15: R105.1@4828.21,1080 4828.21,1021.79 4898.12,951.88 5252.36,951.88 5298.12,997.64 5298.12,1038.12 5340,1080 5670,1080 5677.5,1072.5 U12.7@5677.5,1023.86 ; C112.1@5748.72,999 C112.1@5757.5,999
  Top Layer w20: U12.7@5677.5,1023.86 5710.46,1023.86 5716.19,1018.13 5729.59,1018.13 C112.1@5748.72,999
C0+: D27.3 J7.11 R118.1 | length 572.8
  Top Layer w10: J7.11@762.36,3580 840,3580 887.4,3627.4 D27.3@1012.36,3627.4 1172.6,3627.4 1220,3580 1283.86,3580 R118.1@1292.36,3588.5
C0-: J7.12 R129.2 R131.1 | length 2843.3
  Top Layer w15: v1(1680,4380) v1(1850,4380) ; v1(2040,3970) 2065.55,3944.45 R131.1@2065.55,3903.62
  Top Layer w20: R129.2@453.86,3580 J7.12@662.36,3580
  Bottom Layer w15: J7.12@662.36,3580 560,3580 530,3610 530,3867.65 522.87,3874.78 522.87,4062.87 840,4380 v1(1680,4380) ; v1@1860,4380 v1(1850,4380) 2040,4190 v1(2040,3970)
C1+: D29.3 J7.9 R135.1 | length 1039.4
  Top Layer w10: J7.9@762.36,3480 850,3480 877.4,3507.4 D29.3@1012.36,3507.4 1029.76,3490 1643.86,3490 R135.1@1742.36,3588.5
C1-: J7.10 R128.2 R134.1 | length 3037.1
  Top Layer w15: v1(1860,3860) 1902.32,3902.32 R134.1@1924.45,3902.32
  Top Layer w20: R128.2@453.86,3480 J7.10@662.36,3480
  Bottom Layer w15: J7.10@662.36,3480 530,3480 500,3510 500,4110 800,4410 1664.22,4410 1666.59,4412.37 1693.41,4412.37 1695.78,4410 1750,4410 1860,4300 v1(1860,3860)
C2+: D31.3 J7.7 R152.1 | length 1056.1
  Top Layer w10: J7.7@762.36,3380 764.96,3377.4 D31.3@1012.36,3377.4 1127.4,3377.4 1220,3470 1653.86,3470 R152.1@1742.36,3381.5
C2-: J7.8 R127.2 R141.1 | length 2949.6
  Top Layer w15: v1(1850,3050) 1888.2,3050 R141.1@1895.86,3042.34
  Top Layer w20: R127.2@453.86,3380 J7.8@662.36,3380
  Bottom Layer w15: J7.8@662.36,3380 540,3380 500,3340 500,2710 660,2550 1790,2550 1850,2610 1850,2684.22 1852.37,2686.59 1852.37,2713.41 1850,2715.78 v1(1850,3050)
C3+: D35.3 J7.5 R161.1 | length 580.8
  Top Layer w10: J7.5@762.36,3280 860,3280 882.6,3257.4 D35.3@1012.36,3257.4 1147.4,3257.4 1271.5,3381.5 R161.1@1282.36,3381.5
C3-: J7.6 R126.2 R143.1 | length 2847.5
  Top Layer w15: v1(1730,2590) v1(1930,2590) ; v1(2020,2990) 2020,3006.46 R143.1@2055.88,3042.34
  Top Layer w20: R126.2@453.86,3280 J7.6@662.36,3280
  Bottom Layer w15: J7.6@662.36,3280 550,3280 522.87,3252.87 522.87,2737.13 670,2590 v1(1730,2590) ; v1(1930,2590) 2020,2680 v1(2020,2990)
C4+: D28.3 J7.3 R120.1 | length 874
  Top Layer w10: J7.3@762.36,3180 853.7,3180 906.3,3127.4 D28.3@1032.36,3127.4 1127.6,3127.4 1202,3053 1202,2768 1241.5,2728.5 R120.1@1282.36,2728.5
C4-: J7.4 R125.2 R145.1 | length 2820.1
  Top Layer w15: v1(1800,2630) v1(2160,2630) ; v1(2180,2990) 2180,3012.29 R145.1@2214.09,3046.38
  Top Layer w20: R125.2@453.86,3180 J7.4@662.36,3180
  Bottom Layer w15: J7.4@662.36,3180 580,3180 550,3150 550,2770 690,2630 v1(1800,2630) ; v1(2160,2630) 2180,2650 v1(2180,2990)
C5+: D30.3 J7.1 R137.1 | length 1311.1
  Top Layer w10: J7.1@762.36,3080 844.96,2997.4 D30.3@1012.36,2997.4 1152.6,2997.4 1181,2969 1181,2749 1279.87,2650.13 1683.98,2650.13 R137.1@1742.36,2708.5
C5-: J7.2 R124.2 R147.1 | length 2561.8
  Top Layer w15: v1(1810,2700) 2320,2700 v1(2330,2710) ; v1(2330,2980) 2360.62,3010.62 R147.1@2360.62,3039.95
  Top Layer w20: R124.2@453.86,3080 J7.2@662.36,3080
  Bottom Layer w15: J7.2@662.36,3080 662.36,2787.64 750,2700 1484.22,2700 1496.59,2712.37 1523.41,2712.37 1535.78,2700 v1(1810,2700) ; v1(2330,2710) v1(2330,2980)
C6+: D32.3 J7.15 R154.1 | length 1331.6
  Top Layer w10: J7.15@762.36,3780 800,3780 907.4,3887.4 D32.3@1012.36,3887.4 1047.4,3887.4 1190,4030 1190,4190 1300,4300 1673.86,4300 R154.1@1752.36,4221.5
C6-: J7.16 R123.2 R149.1 | length 2736.5
  Top Layer w15: v1(1820,4290) v1(2290,4290) ; v1(2330,3960) 2362.57,3927.43 R149.1@2362.57,3903.06
  Top Layer w20: R123.2@453.86,3780 J7.16@662.36,3780
  Bottom Layer w15: J7.16@662.36,3780 620,3780 590,3810 590,4010 860,4280 1480,4280 1502.37,4302.37 1573.41,4302.37 1575.78,4300 1760,4300 1770,4290 v1(1820,4290) ; v1(2290,4290) 2330,4250 v1(2330,3960)
C7+: D34.3 J7.13 R157.1 | length 952.4
  Top Layer w10: J7.13@762.36,3680 840.31,3680 917.72,3757.4 D34.3@1012.36,3757.4 1107.4,3757.4 1217,3867 1217,3969.75 1214.13,3972.63 1214.13,3997.37 1217,4000.25 1217,4177 1271.5,4231.5 R157.1@1302.36,4231.5
C7-: J7.14 R122.2 R151.1 | length 2829.3
  Top Layer w15: v1(1750,4340) 2110,4340 v1(2140,4340) ; v1(2180,3970) 2212.57,3937.43 R151.1@2212.57,3900.78
  Top Layer w20: R122.2@453.86,3680 J7.14@662.36,3680
  Bottom Layer w15: J7.14@662.36,3680 584.72,3680 564.72,3700 564.72,3870.03 565.75,3871.05 565.75,4041.34 864.41,4340 v1(1750,4340) ; v1(2140,4340) 2150,4340 2180,4310 v1(2180,3970)
CO0+: C126.1 R130.1 U16.8 U16.9 | length 1190.5
  Top Layer w10: U16.8@1445.59,3783.86 1445.59,3750.87 1450,3746.46 1470,3746.46 1471.18,3747.64 U16.9@1471.18,3783.86
  Top Layer w15: U16.8@1445.59,3783.86 1445.59,3825.59 1470,3850 1750,3850 1920,4020 2130,4020 2150,4000 2150,3985.78 2147.63,3983.41 2147.63,3956.59 2150,3954.22 2150,3906.19 R130.1@2145.55,3901.74
  Top Layer w20: C126.1@1292.36,3791.5 1300,3783.86 U16.8@1445.59,3783.86
CO1+: C135.1 R132.1 U16.13 U16.14 | length 629.1
  Top Layer w10: U16.13@1573.54,3783.86 1573.54,3752.91 1580,3746.46 1596.46,3746.46 1600,3750 1599.13,3750.87 U16.14@1599.13,3783.86
  Top Layer w15: C135.1@1742.36,3791.5 1742.36,3802.36 1900,3960 1990,3960 2004.45,3945.55 R132.1@2004.45,3902.88
  Top Layer w20: U16.14@1599.13,3783.86 1734.72,3783.86 C135.1@1742.36,3791.5
CO2+: C145.1 R139.1 U17.1 U17.2 | length 639.9
  Top Layer w10: U17.2@1563.54,3166.14 1563.54,3197.09 1570,3203.54 1580,3203.54 1589.13,3194.41 U17.1@1589.13,3166.14
  Top Layer w15: C145.1@1742.36,3178.5 1742.36,3107.64 1860,2990 1950,2990 1975.86,3015.86 R139.1@1975.86,3042.34
  Top Layer w20: U17.1@1589.13,3166.14 1730,3166.14 C145.1@1742.36,3178.5
CO3+: C151.1 R142.1 U17.6 U17.7 | length 1153.8
  Top Layer w10: U17.7@1435.59,3166.14 1435.59,3199.13 1440,3203.54 1460,3203.54 1461.18,3202.36 U17.6@1461.18,3166.14
  Top Layer w15: U17.7@1435.59,3166.14 1435.59,3124.41 1450,3110 1650,3110 1660,3100 1690,3100 1840,2950 2121.77,2950 2135.88,2964.12 R142.1@2135.88,3042.34
  Top Layer w20: C151.1@1282.36,3178.5 1294.72,3166.14 U17.7@1435.59,3166.14
CO4+: C127.1 R144.1 U17.8 U17.9 | length 1277.7
  Top Layer w10: U17.8@1435.59,2933.86 1435.59,2900.87 1440,2896.46 1460,2896.46 1461.18,2897.64 U17.9@1461.18,2933.86
  Top Layer w15: 1450,2990 1760,2990 1820,2930 1827.65,2930 1830.53,2927.13 2139.47,2927.13 2142.35,2930 2258.18,2930 2294.09,2965.91 R144.1@2294.09,3043.98
  Top Layer w20: C127.1@1282.36,2931.5 1284.72,2933.86 U17.8@1435.59,2933.86 1435.59,2975.59 1450,2990
CO5+: C136.1 R146.1 U17.13 U17.14 | length 1081.9
  Top Layer w10: U17.13@1563.54,2933.86 1563.54,2902.91 1570,2896.46 1580,2896.46 1589.13,2905.59 U17.14@1589.13,2933.86
  Top Layer w15: C136.1@1742.36,2921.5 1778.5,2921.5 1810,2890 2390,2890 2442.36,2942.36 R146.1@2442.36,3039.95
  Top Layer w20: U17.14@1589.13,2933.86 1730,2933.86 C136.1@1742.36,2921.5
CO6+: C146.1 R148.1 U16.1 U16.2 | length 1089.6
  Top Layer w10: U16.2@1573.54,4016.14 1573.54,4047.09 1580,4053.54 1590,4053.54 1599.13,4044.41 U16.1@1599.13,4016.14
  Top Layer w15: C146.1@1752.36,4018.5 1808.5,4018.5 1870,4080 2360,4080 2442.36,3997.64 R148.1@2442.36,3903.06
  Top Layer w20: U16.1@1599.13,4016.14 1750,4016.14 C146.1@1752.36,4018.5
CO7+: C150.1 R150.1 U16.6 U16.7 | length 1305.1
  Top Layer w10: U16.7@1445.59,4016.14 1445.59,4049.13 1450,4053.54 1466.46,4053.54 1471.18,4048.82 U16.6@1471.18,4016.14
  Top Layer w15: U16.7@1445.59,4016.14 1445.59,3964.41 1460,3950 1810,3950 1910,4050 2235.14,4050 2292.57,3992.57 R150.1@2292.57,3900.78
  Top Layer w20: C150.1@1302.36,4028.5 1314.72,4016.14 U16.7@1445.59,4016.14
CS1: J5.3 R42.1 U3.38 | length 5466.4
  Top Layer w10: U3.38@2715.42,5173.86 2715.42,5124.58 2738.5,5101.5 2750,5101.5 ; R42.1@2790,5101.5 2750,5101.5 ; J5.3@4540,510 4540,820 3340,2020 3340,4370 2763.62,4946.38 2763.62,4954.81 2750,4968.43 2750,5101.5
CS2: J5.4 R114.1 U14.38 | length 1565
  Top Layer w10: v1(4320,1590) 4390,1590 4405.79,1605.79 U14.38@4405.79,1610 ; R114.1@4352.05,1768.5 4350,1766.46 4350,1710 4404.88,1655.12 U14.38@4404.88,1636.14
  Bottom Layer w10: v1(4320,1590) 4320,1080 4590,810 4590,620 4587.87,617.87 4587.87,457.87 J5.4@4540,410
CS3: J5.13 R159.1 U18.38 | length 3538.8
  Top Layer w10: R159.1@2802.36,3271.5 2802.36,3307.64 2756.2,3353.8 U18.38@2727.79,3353.8 2727.79,3258.05 2745.75,3240.08 2745.75,3174.25 2850,3070 2850,3060.56 2880.13,3030.43 2880.13,3017.63 2897.63,3000.13 2910.43,3000.13 3204,2706.56 3204,1901.28 4040,1065.28 J5.13@4040,510 J5.13@4050,520
CS4: J5.14 R204.1 U22.38 | length 3737.9
  Top Layer w10: v1(4330,3530) 4402.05,3602.05 ; R204.1@4402.05,3628.5 4402.05,3602.05 ; U22.38@4474.88,3486.46 4474.88,3525.12 4402.05,3597.95 4402.05,3602.05
  Bottom Layer w10: J5.14@4040,410 4090,460 4090,1400 3820,1670 3820,3020 v1(4330,3530)
CS5: J5.23 R249.1 U26.38 | length 1202
  Top Layer w10: U26.38@2925.42,1403.81 2925.42,1334.58 2940,1320 2960,1320 ; R249.1@3000,1321.5 2998.5,1320 2960,1320 ; J5.23@3540,510 3540,640 3119.87,1060.13 3117.63,1060.13 3100.13,1077.63 3100.13,1079.87 2960,1220 2960,1320
CS6: J5.24 R294.1 U30.38 | length 5661.3
  Top Layer w10: v1(4402,5505) v1@4405,5505 ; R294.1@4420,5570.94 4420,5520 v1@4405,5505 ; U30.38@4484.72,5424.72 4484.72,5452.84 4484.44,5453.13 4483.63,5453.13 4466.13,5470.63 4466.13,5471.44 4432.56,5505 v1@4405,5505
  Bottom Layer w10: J5.24@3540,410 3596.15,466.15 3596.15,486.15 3592.13,490.17 3592.13,533.85 3596.15,537.87 3596.15,786.15 3600,790 3600,4680.75 4210.13,5290.88 4210.13,5292.37 4227.63,5309.87 4229.12,5309.87 4402,5482.75 v1(4402,5505)
D0+: D36.3 J8.11 R163.1 | length 577.6
  Top Layer w10: R163.1@5852.05,3311.5 5853.54,3310 5950,3310 5962.6,3297.4 D36.3@6152.05,3297.4 6277.09,3297.4 6329.69,3350 J8.11@6402.05,3350
D0-: J8.12 R174.2 R176.1 | length 3080.8
  Top Layer w15: R176.1@5101.81,2936.38 5101.81,2898.19 v1(5130,2870) ; v1(5200,2510) v1(5410,2510)
  Top Layer w20: J8.12@6502.05,3350 R174.2@6710.55,3350
  Bottom Layer w15: v1(5130,2870) 5130,2580 v1(5200,2510) ; v1(5410,2510) 5427.13,2492.87 6592.87,2492.87 6650,2550 6650,3310 6610,3350 J8.12@6502.05,3350
D1+: D38.3 J8.9 R180.1 | length 1081.9
  Top Layer w10: R180.1@5392.05,3301.5 5530.55,3440 6129.45,3440 D38.3@6142.05,3427.4 6297.09,3427.4 6319.69,3450 J8.9@6402.05,3450
D1-: J8.10 R173.2 R179.1 | length 3196.8
  Top Layer w15: R179.1@5241.81,2936.38 5266.38,2936.38 v1(5300,2970)
  Top Layer w20: J8.10@6502.05,3450 R173.2@6710.55,3450
  Bottom Layer w15: v1(5300,2970) 5300,2540 5370,2470 6610,2470 6682.07,2542.07 6682.07,3377.2 6609.27,3450 J8.10@6502.05,3450
D2+: D40.3 J8.7 R197.1 | length 1061.8
  Top Layer w10: R197.1@5412.05,3528.5 5470.55,3470 5900,3470 5997.4,3567.4 D40.3@6142.05,3567.4 6384.65,3567.4 J8.7@6402.05,3550
D2-: J8.8 R172.2 R186.1 | length 3035.7
  Top Layer w15: R186.1@5291.95,3815.43 5297.38,3810 v1(5350,3810)
  Top Layer w20: J8.8@6502.05,3550 R172.2@6710.55,3550
  Bottom Layer w15: v1(5350,3810) 5350,4320 5410,4380 5514.22,4380 5516.59,4382.37 5543.41,4382.37 5545.78,4380 6550,4380 6670,4260 6670,3580 6640,3550 J8.8@6502.05,3550
D3+: D44.3 J8.5 R206.1 | length 651
  Top Layer w10: R206.1@5882.05,3538.5 5930,3586.46 5930,3650 5987.4,3707.4 D44.3@6142.05,3707.4 6292.28,3707.4 6349.69,3650 J8.5@6402.05,3650
D3-: J8.6 R171.2 R188.1 | length 2919.3
  Top Layer w15: R188.1@5146,3812.63 5180,3846.63 v1(5180,3870) ; v1(5270,4350) 5424.22,4350 5426.59,4352.37 5453.41,4352.37 5455.78,4350 v1(5530,4350)
  Top Layer w20: J8.6@6502.05,3650 R171.2@6710.55,3650
  Bottom Layer w15: v1(5180,3870) 5180,4260 v1(5270,4350) ; v1(5530,4350) 6530,4350 6640,4240 6640,3690 6600,3650 J8.6@6502.05,3650
D4+: D37.3 J8.3 R165.1 | length 787.5
  Top Layer w10: R165.1@5872.05,4161.5 6003,4030.54 6003,3882 6047.6,3837.4 D37.3@6142.05,3837.4 6252.28,3837.4 6339.69,3750 J8.3@6402.05,3750
D4-: J8.4 R170.2 R190.1 | length 2850.3
  Top Layer w15: R190.1@5000,3815.43 5000,3830 v1(5040,3870) ; v1(5160,4320) 5254.22,4320 5256.59,4317.63 5283.41,4317.63 5285.78,4320 v1(5440,4320)
  Top Layer w20: J8.4@6502.05,3750 R170.2@6710.55,3750
  Bottom Layer w15: v1(5040,3870) 5040,4200 v1(5160,4320) ; v1(5440,4320) 5441.17,4318.83 5515.39,4318.83 5516.59,4317.63 5543.41,4317.63 5544.61,4318.83 6528.83,4318.83 6610,4237.65 6610,3770 6590,3750 J8.4@6502.05,3750
D5+: D39.3 J8.1 R182.1 | length 1237.6
  Top Layer w10: R182.1@5412.05,4161.5 5490.43,4239.87 5630.26,4239.87 5670.14,4200 5920,4200 6035,4085 6035,3995 6061,3969 6061,3967.4 D39.3@6142.05,3967.4 6284.65,3967.4 J8.1@6402.05,3850
D5-: J8.2 R169.2 R192.1 | length 2560.6
  Top Layer w15: R192.1@4850,3815.43 4850,3830 v1(4890,3870) ; v1(5040,4280) 5050,4270 v1(5410,4270)
  Top Layer w20: J8.2@6502.05,3850 R169.2@6710.55,3850
  Bottom Layer w15: v1(4890,3870) 4890,4130 v1(5040,4280) ; v1(5410,4270) 6370,4270 6502.05,4137.95 J8.2@6502.05,3850
D6+: D41.3 J8.15 R199.1 | length 1397.3
  Top Layer w10: R199.1@5392.05,2668.5 5396.09,2668.5 5464.47,2600.13 5840.13,2600.13 6008,2768 6008,2992 6043.4,3027.4 D41.3@6152.05,3027.4 6279.45,3027.4 J8.15@6402.05,3150
D6-: J8.16 R168.2 R194.1 | length 2911.2
  Top Layer w15: R194.1@4821.81,2935.08 4821.81,2898.19 v1(4850,2870) ; v1(4850,2670) 4920,2600 5362.05,2600 5379.67,2582.37 5453.41,2582.37 5456.03,2579.75 5490.25,2579.75 5500,2570 v1(5560,2570)
  Top Layer w20: J8.16@6502.05,3150 R168.2@6710.55,3150
  Bottom Layer w15: v1(4850,2670) v1(4850,2870) ; v1(5560,2570) 5560,2580 6550,2580 6597.13,2627.13 6597.13,3132.87 6580,3150 J8.16@6502.05,3150
D7+: D43.3 J8.13 R202.1 | length 986.6
  Top Layer w10: R202.1@5850,2688.5 5874.7,2688.5 5877.2,2686 5978,2786.8 5978,3128 6007.4,3157.4 D43.3@6152.05,3157.4 6257.09,3157.4 6349.69,3250 J8.13@6402.05,3250
D7-: J8.14 R167.2 R196.1 | length 2989.8
  Top Layer w15: R196.1@4960.02,2936.38 4960.02,2899.98 v1(4990,2870) ; v1(5060,2550) v1(5440,2550)
  Top Layer w20: J8.14@6502.05,3250 R167.2@6710.55,3250
  Bottom Layer w15: v1(4990,2870) 4990,2620 v1(5060,2550) ; v1(5440,2550) 5460,2530 6570,2530 6620,2580 6620,3210 6580,3250 J8.14@6502.05,3250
